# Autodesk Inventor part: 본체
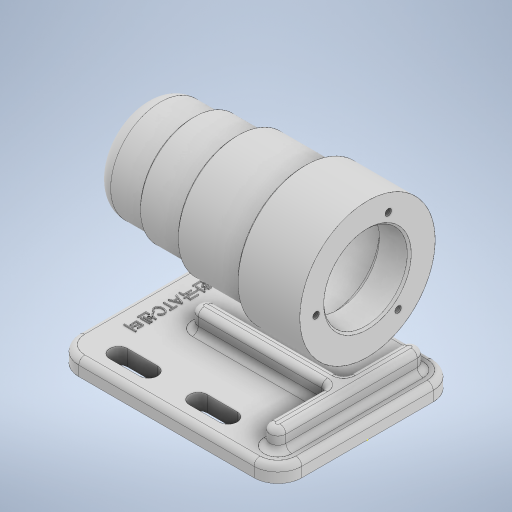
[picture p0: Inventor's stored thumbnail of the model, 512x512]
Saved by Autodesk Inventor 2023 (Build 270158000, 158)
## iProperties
Created: 2022-07
Part Number: 본체
Material: 일반
Document SubType Name: Modeling
Designer: owner
Density: 1 g/cm^3
Appearance: 기본값
Author: owner
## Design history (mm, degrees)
sketch "스케치1"
  geometry: L1 (56, -45)-(-56, -45); L2 (-56, -45)-(-56, 45); L3 (-56, 45)-(56, 45); L4 (56, 45)-(56, -45); L5 (56, -45)-(-56, 45); L6 (-56, -45)-(56, 45); L7 (56, 0)-(-56, 0); L8 (36, -33)-(21, -33); L9 (36, -28.5)-(21, -28.5); L10 (21, -37.5)-(36, -37.5); L11 (-4, -33)-(-19, -33); L12 (-4, -28.5)-(-19, -28.5); L13 (-19, -37.5)-(-4, -37.5); L14 (36, 28.5)-(21, 28.5); L15 (21, 37.5)-(36, 37.5); L16 (-19, 37.5)-(-4, 37.5); L17 (-4, 28.5)-(-19, 28.5); A1 r 4.5 centre (36, -33) between (36, -37.5) and (36, -28.5); A2 r 4.5 centre (21, -33) between (21, -28.5) and (21, -37.5); A3 r 4.5 centre (-4, -33) between (-4, -37.5) and (-4, -28.5); A4 r 4.5 centre (-19, -33) between (-19, -28.5) and (-19, -37.5); A5 r 4.5 centre (21, 33) between (21, 37.5) and (21, 28.5); A6 r 4.5 centre (36, 33) between (36, 28.5) and (36, 37.5); A7 r 4.5 centre (-4, 33) between (-4, 28.5) and (-4, 37.5); A8 r 4.5 centre (-19, 33) between (-19, 37.5) and (-19, 28.5); 3 further points
  constraints: 38 end point, 16 point on circle, 12 symmetric about line, 8 centre point, 8 tangent, 6 midpoint, 5 parallel, 2 horizontal, 1 horizontal alignment, 1 perpendicular, 4 other
  dimensions: "d0" = 112 distance of L2.end L3.end; "d1" = 90 distance of L1.end L2.end; "d2" = 9 diameter of A4; "d3" = 9 distance between parallel lines of L9 L10; "d4" = 15 distance of L8.end L8.start; "d5" = 15 distance of L11.end L11.start; "d6" = 20 distance from line of L4 L8.start; "d7" = 25 distance of L11.start L8.end; "d8" = 33 distance between parallel lines of L7 L11
extrude "돌출1" new body sketch "스케치1" distance "d9" = 8; taper "d10" = 0 deg
sketch "스케치2"
  geometry: L1 (-56, 8)-(56, 8) reference; L2 (-56, 0)-(-56, 8) reference; L3 (56, 104)-(25, 104); L4 (24, 103)-(24, 100); L5 (24, 100)-(-9, 100); L6 (-10, 99)-(-10, 97); L7 (-10, 97)-(-31, 97); L8 (-32, 96)-(-32, 95); L9 (-32, 95)-(-48, 95); L10 (-56, 87)-(-56, 70); L11 (56, 104)-(56, 92); L12 (-56, 70)-(56, 70); L13 (-56, 0)-(56, 0) reference; L14 (-31, 97)-(-32, 96); L15 (-9, 100)-(-10, 99); L16 (25, 104)-(24, 103); L17 (-25, 87.5)-(-43, 87.5); L18 (-43, 87.5)-(-43, 86); L19 (-43, 86)-(-45.057, 86); L20 (-45.057, 86)-(-45.057, 80.5); L21 (-45.057, 80.5)-(-46.5, 80.5); L22 (-49.5, 77.5)-(-49.5, 70); L23 (-25, 87.5)-(-25, 91); L24 (-25, 91)-(-13, 91); L25 (41, 91)-(41, 91); L26 (41, 91)-(55, 91); L27 (55, 91)-(56, 92); L28 (56, 92)-(56, 70); L29 (-13, 91)-(-13, 91); L30 (-10, 94)-(38, 94); A1 r 8 centre (-48, 87) between (-48, 95) and (-56, 87); A2 r 3 centre (-10, 91) between (-10, 94) and (-13, 91); A3 r 3 centre (38, 91) between (41, 91) and (38, 94); A4 r 3 centre (-46.5, 77.5) between (-46.5, 80.5) and (-49.5, 77.5); 10 further points
  constraints: 54 end point, 12 perpendicular, 12 point on line, 8 point on circle, 8 tangent, 4 centre point, 4 horizontal, 3 vertical, 2 equal radius, 2 midpoint
  dimensions: "d15" = 112 distance between parallel lines of L11 L10; "d16" = 50 diameter of L9 L12; "d17" = 54 diameter of L7 L12; "d18" = 60 diameter of L5 L12; "d19" = 68 diameter of L3 L12; "d20" = 8 radius of A1; "d21" = 24 distance between parallel lines of L8 L10; "d22" = 46 distance between parallel lines of L6 L10; "d23" = 80 distance between parallel lines of L4 L10; "d24" = 70 distance between parallel lines of L13 L12; "d25" = 1 distance of L7.end point (-32, 97); "d26" = 1 distance of L8.start point (-32, 97) (= d25); "d27" = 1 distance of L5.end point (-10, 100) (= d25); "d28" = 1 distance of L6.start point (-10, 100) (= d27); "d29" = 1 distance of L3.end point (24, 104) (= d25); "d30" = 1 distance of L4.start point (24, 104) (= d29); "d31" = 56 distance from line of L10 point (0, 0); "d32" = 21 diameter of L21 L12; "d33" = 32 diameter of L19 L12; "d34" = 35 diameter of L17 L12; "d35" = 42 diameter of L24 L12; "d37" = 42 diameter of L26 L12; "d41" = 1 distance of L26.end point (56, 91) (= d39); "d42" = 1 distance of L11.end point (56, 91) (= d41); "d45" = 15 distance between parallel lines of L11 L25; "d48" = 12 distance between parallel lines of L23 L29; "d52" = 18 distance of L17.end L17.start; "d53" = 24.5 distance between parallel lines of L23 L22; "d54" = 4.44268 distance between parallel lines of L20 L22; "d55" = 3 radius of A2; "d56" = 46 distance from line of L10 L30.start; "d57" = 48 diameter of L30 L12
revolve "회전1" sketch "스케치2" stored, may be unused: angle "d58" = 90 deg
sketch "스케치3"
  geometry: L1 (56, -45)-(56, 45) reference; L2 (-56, 45)-(-56, -45) reference; L3 (-56, -45)-(56, -45) reference; L4 (-56, 45)-(-56, -45) reference; L5 (56, 45)-(-56, 45) reference; L6 (56, -45)-(56, 45) reference; L7 (19, -37.5)-(4, -37.5) reference; L8 (4, -28.5)-(19, -28.5) reference; L9 (-21, -37.5)-(-36, -37.5) reference; L10 (-36, -28.5)-(-21, -28.5) reference; L11 (19, 28.5)-(4, 28.5) reference; L12 (4, 37.5)-(19, 37.5) reference; L13 (-21, 28.5)-(-36, 28.5) reference; L14 (-36, 37.5)-(-21, 37.5) reference; L15 (-25, 0)-(44, 0); L16 (-25, -4)-(44, -4); L17 (44, 4)-(-25, 4); L18 (44, 33)-(44, -33); L19 (40, 33)-(40, -33); L20 (48, -33)-(48, 33); L21 (-56, 0)-(56, 0); A1 r 4.5 centre (19, -33) between (19, -37.5) and (19, -28.5) reference; A2 r 4.5 centre (4, -33) between (4, -28.5) and (4, -37.5) reference; A3 r 4.5 centre (-21, -33) between (-21, -37.5) and (-21, -28.5) reference; A4 r 4.5 centre (-36, -33) between (-36, -28.5) and (-36, -37.5) reference; A5 r 4.5 centre (4, 33) between (4, 37.5) and (4, 28.5) reference; A6 r 4.5 centre (19, 33) between (19, 28.5) and (19, 37.5) reference; A7 r 4.5 centre (-36, 33) between (-36, 37.5) and (-36, 28.5) reference; A8 r 4.5 centre (-21, 33) between (-21, 28.5) and (-21, 37.5) reference; A9 r 4 centre (-25, 0) between (-25, 4) and (-25, -4); A10 r 4 centre (44, 0) between (44, -4) and (44, 4); A11 r 4 centre (44, 33) between (48, 33) and (40, 33); A12 r 4 centre (44, -33) between (40, -33) and (48, -33); 7 further points
  constraints: 18 end point, 9 point on circle, 8 tangent, 6 midpoint, 4 centre point, 2 parallel, 1 horizontal, 1 perpendicular, 1 point on line, 1 vertical
  dimensions: "d81" = 8 distance between parallel lines of L20 L19; "d82" = 8 distance between parallel lines of L16 L17; "d83" = 77 distance from line of L20 point (-29, 0); "d84" = 8 distance between parallel lines of L1 L20; "d85" = 33 distance from line of L18.end L21; "d86" = 66 distance of L18.end L18.start
extrude "돌출2" join sketch "스케치3" distance "d69" = 10; taper "d70" = 0 deg
sketch "스케치8"
  geometry: 1 further point
sketch "스케치9"
  geometry: C1 r 7.5 at (0, 0) reference; A1 r 26 centre (0, 0) between (-25.844, -2.842) and (15.383, -20.961); 3 further points
  constraints: 2 point on circle, 1 centre point, 1 coincident, 2 other
  dimensions: "d94" = 52 diameter of A1; "d95" = 120 deg dimension on A1.centre A1.start point (10.461, 23.803); "d96" = 120 deg dimension on A1.centre A1.end A1.start
hole "구멍1" sketch "스케치9" at (10.461, 23.803), (-25.844, -2.842), (15.383, -20.961) diameter "d97" = 3.242; stored, may be unused: countersink angle "d101" = 90 deg, drill point angle "d103" = 118 deg; dims "d98" = 8, "d99" = 4, "d100" = 2, "d102" = 11
fillet "모깎기1" dims "d104" = 12
fillet "모깎기2" dims "d105" = 3
sketch "스케치10"
  geometry: L1 (-36, -28.5)-(-21, -28.5) reference; L2 (-56, 33)-(-56, -33) reference; A1 r 4.5 centre (-36, -33) between (-36, -28.5) and (-36, -37.5) reference; 2 further points
  constraints: 1 other
  dimensions: "d106" = 33 vertical distance of point (-44, 0) A1.centre; "d107" = 12 distance from line of point (-44, 0) L2
feature "엠보싱1" sketch "스케치10" dims "d0" = 112, "d1" = 90, "d2" = 9, "d3" = 9, "d4" = 15, "d5" = 15, "d6" = 20, "d7" = 25, "d8" = 33, "d108" = 0.5, "d109" = 0
node "솔리드1"
node "투영된 루프1"
feature "A9D066F2-1C7D-4E18-AEED-F7BC21143FA4" dims "d97" = 3.242, "d98" = 8, "d99" = 4, "d100" = 2, "d101" = 90 deg, "d102" = 11, "d103" = 118 deg
other parameters: "d39" = 1, "d65" = 8
